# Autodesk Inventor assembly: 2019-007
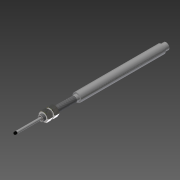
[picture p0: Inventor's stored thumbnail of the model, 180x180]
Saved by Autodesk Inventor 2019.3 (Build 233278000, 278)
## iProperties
Category: SENSORS
Company: TSC
Created: 2019-02
Part Number: 2019-007
Document SubType Name: Weldment
Designer: J. Nielson
Weld Material: Stainless Steel
Mass: 67.262 g
Surface Area: 355.176 cm^2
Volume: 33.1531 cm^3
Density: 2.02883 g/cm^3
Author: Justin
Title: GH-750-A-1000
Keywords: LVDT, POSITION, SENSOR
Revision Number: -
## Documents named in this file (4)
- C:\Users\Justin\Documents\CAD Drawings\The Sensor Connection\3D\LVDT\GH SERIES\GH-750-A-XXXX\GH-750-A-1000\GH-750-A-1000 ASS'Y.iam
- C:\Users\Justin\Documents\CAD Drawings\The Sensor Connection\3D\LVDT\GH SERIES\GH-750-A-XXXX\GH-750-A-1000\GH-750-A-1000 SHAFT_SW.ipt
- C:\Users\Justin\Documents\CAD Drawings\The Sensor Connection\3D\LVDT\GH SERIES\GH-750-A-XXXX\GH-750-A-1000\GH-750-A-1000 HOUSING_SW.ipt
- C:\Users\Justin\Documents\CAD Drawings\The Sensor Connection\3D\LVDT\GH SERIES\GH-750-A-XXXX\GH-750-A-1000\AS 2465 - 1_2  UNF(1).ipt
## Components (4 placed, 3 different names)
1. GH-750-A-1000 HOUSING_SW:1 — Mate:1, Cylindrical:1, Mate:4, Flush:1
2. GH-750-A-1000 SHAFT_SW:1 — Mate:1, Cylindrical:1
3. AS 2465 - Inch 1/2  UNF:1 — Mate:2, Mate:3, Mate:4, Flush:1, Angle:1
4. AS 2465 - Inch 1/2  UNF:2 — Mate:2, Mate:3, Angle:1, Angle:2
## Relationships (8: Mate 4, Angle 2, CylindricalJoint 1, Flush 1)
- Mate:1: GH-750-A-1000 HOUSING_SW:1 ↔ GH-750-A-1000 SHAFT_SW:1
- Cylindrical:1: GH-750-A-1000 HOUSING_SW:1 ↔ GH-750-A-1000 SHAFT_SW:1
- Mate:2: AS 2465 - Inch 1/2  UNF:1 ↔ AS 2465 - Inch 1/2  UNF:2
- Mate:3: AS 2465 - Inch 1/2  UNF:1 ↔ AS 2465 - Inch 1/2  UNF:2
- Mate:4: GH-750-A-1000 HOUSING_SW:1 ↔ AS 2465 - Inch 1/2  UNF:1
- Flush:1: GH-750-A-1000 HOUSING_SW:1 ↔ AS 2465 - Inch 1/2  UNF:1
- Angle:1: AS 2465 - Inch 1/2  UNF:1 ↔ AS 2465 - Inch 1/2  UNF:2
- Angle:2: AS 2465 - Inch 1/2  UNF:2
